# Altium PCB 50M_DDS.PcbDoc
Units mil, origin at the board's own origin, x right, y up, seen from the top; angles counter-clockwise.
Board outline 3260 x 1620 mil, 2 copper layers (Top Layer, Bottom Layer); 21 components, 21 nets, 79 pads, 5 vias.
Unrouted connection lines stored in the file: 2.
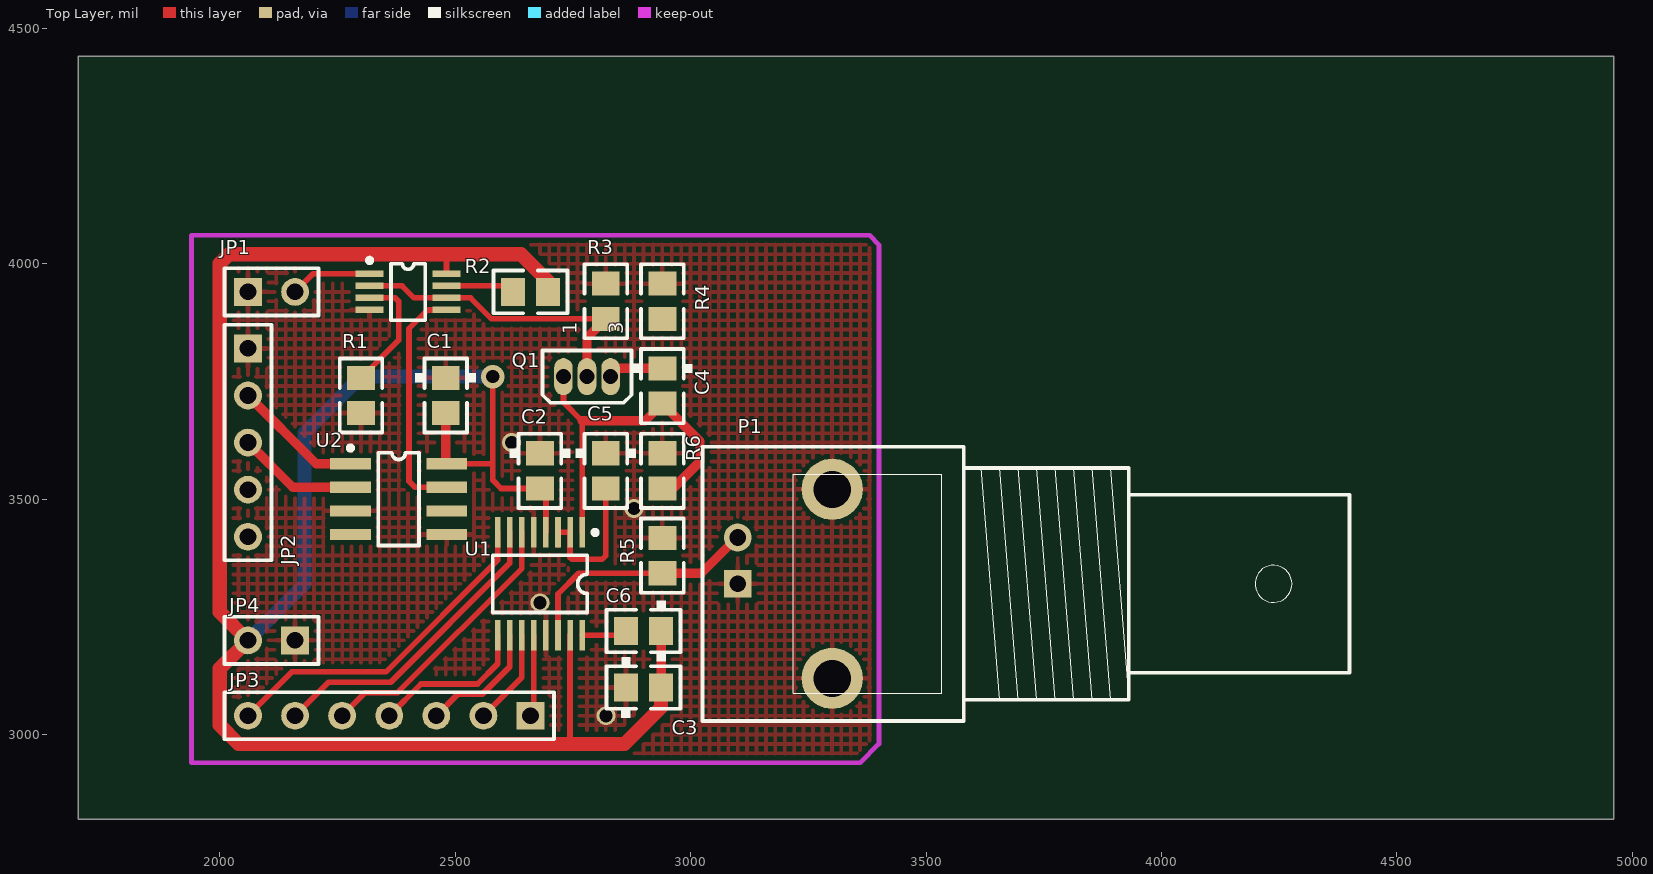
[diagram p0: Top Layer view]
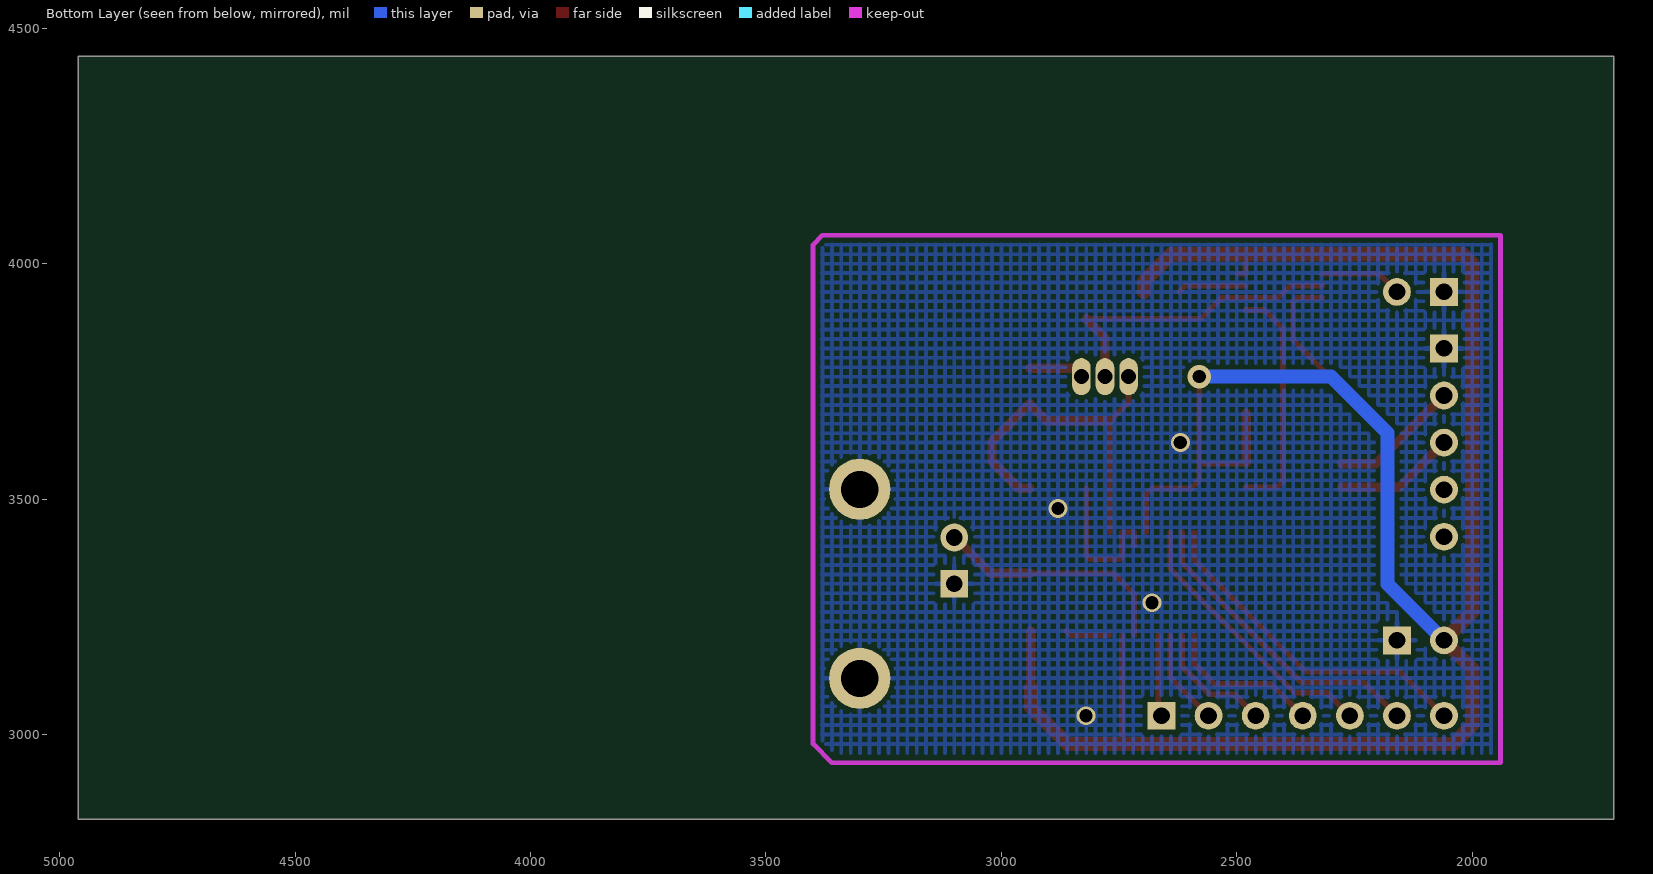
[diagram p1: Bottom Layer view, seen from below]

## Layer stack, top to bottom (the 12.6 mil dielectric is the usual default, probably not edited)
Top Layer: signal copper 1.4
Dielectric: dielectric 12.6, FR-4, Dk 4.8
Bottom Layer: signal copper 1.4

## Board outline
1700,4380 1700,2820 4960,2820 4960,4440 1700,4440

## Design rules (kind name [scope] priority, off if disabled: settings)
Clearance [All] p1: gap=10
ComponentClearance [All] p1: gap=10 collisioncheckmode=0
PolygonConnect [All] p1: connectstyle=Relief reliefconductorwidth=10 reliefentries=4 polygonreliefangle="90 Angle"
RoutingLayers [All] p1: top layer=Horizontal bottom layer=Vertical
RoutingVias [All] p1: holewidth=28 width=50 viastyle="Through Hole" minholewidth=28 minwidth=50 maxholewidth=28 maxwidth=50
SolderMaskExpansion [All] p1: expansion=4
TestPointUsage [All] p1: valid=0 allowmultiple=FALSE
Testpoint [All] p1: side=15 testpointundercomponent=TRUE minsize=40 maxsize=100 preferedsize=60 minholesize=0 maxholesize=40 preferedholesize=32 testpointgrid=1 style=1023 order=1234567890
Width [All] p1: maxlimit=50 minlimit=10 preferedwidth=10 toplayer_prefwidth=12 bottomlayer_prefwidth=30 minimp=50.000000 maximp=50.000000 favimp=50.000000
16 further rules are at their usual default settings.

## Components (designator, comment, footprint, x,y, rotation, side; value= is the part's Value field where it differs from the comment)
C1 "100pF" CC2012-0805 2480,3720 r270 top
C2 "100pF" CC2012-0805 2680,3560 r270 top
C3 "100pF" CC2012-0805 2900,3100 r0 top
C4 "510pF" CC2012-0805 2940,3740 r270 top
C5 "100pF" CC2012-0805 2820,3560 r270 top
C6 "100pF" CC2012-0805 2900,3220 r180 top
JP1 "Header 2" HDR1X2 2060,3940 r0 top locked
JP2 "Header 5" HDR1X5 2060,3820 r270 top locked
JP3 "Header 7" HDR1X7 2660,3040 r180 top locked
JP4 "Header 2" HDR1X2 2160,3200 r180 top locked
P1 "BNC" "BNC_RA CON" 3100,3320 r180 top
Q1 "MOSFET-N" BCY-W3/H.8 2780,3760 r90 top
R1 "4.7K" R2012-0805 2300,3720 r270 top
R2 "4.7K" R2012-0805 2660,3940 r0 top
R3 "50" R2012-0805 2820,3920 r270 top
R4 "1.5K" R2012-0805 2940,3920 r270 top
R5 "300" R2012-0805 2940,3380 r270 top
R6 "4.7K" R2012-0805 2940,3560 r270 top
U1 "AD9835" TSSO5X6-G16 2680,3320 r180 top
U2 "TLC5615" SO-G8 2380,3500 r270 top
? "ADG821" TSSO3X5-G8/X.35 2400,3940 r270 top

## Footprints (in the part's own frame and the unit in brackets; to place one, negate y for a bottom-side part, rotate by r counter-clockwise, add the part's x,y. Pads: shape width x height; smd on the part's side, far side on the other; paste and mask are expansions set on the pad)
BCY-W3/H.8 [mm]
  oval 2x1 hole 0.8: 1(0,1.27) 2(0,0) 3(0,-1.27)
  silkscreen extent -1.41,-2.41 1.41,2.41
"BNC_RA CON" [mm]
  rect 1.5x1.5 hole 0.9: 1(0,0)
  round 3.3 hole 2: 2(-5.1,5.1) 2(-5.1,-5.1)
  round 1.5 hole 0.9: 2(0,-2.5)
  silkscreen extent -33,-7.4 1.9,7.4
CC2012-0805 [mm]
  rect 1.3x1.5 smd: 1(-0.95,0) 2(0.95,0)
  silkscreen extent -2,-1.65 2,1.64
HDR1X2 [mm]
  rect 1.5x1.5 hole 0.9: 1(0,0)
  round 1.5 hole 0.9: 2(2.54,0)
  silkscreen extent -1.27,-1.27 3.81,1.27
HDR1X5 [mm]
  rect 1.5x1.5 hole 0.9: 1(0,0)
  round 1.5 hole 0.9: 2(2.54,0) 3(5.08,0) 4(7.62,0) 5(10.16,0)
  silkscreen extent -1.27,-1.27 11.43,1.27
HDR1X7 [mm]
  rect 1.5x1.5 hole 0.9: 1(0,0)
  round 1.5 hole 0.9: 2(2.54,0) 3(5.08,0) 4(7.62,0) 5(10.16,0) 6(12.7,0) 7(15.24,0)
  silkscreen extent -1.27,-1.27 16.51,1.27
R2012-0805 [mm]
  rect 1.3x1.5 smd: 1(-0.95,0) 2(0.95,0)
  silkscreen extent -2,-1.15 2,1.15
SO-G8 [mm]
  rect 0.6x2.2 smd: 1(-1.905,-2.6) 2(-0.635,-2.6) 3(0.635,-2.6) 4(1.905,-2.6) 5(1.905,2.6) 6(0.635,2.6) 7(-0.635,2.6) 8(-1.905,2.6)
  silkscreen extent -2.88,-2.72 2.5,1.1
TSSO3X5-G8/X.35 [mm]
  rect 0.35x1.5 smd: 1(-0.975,-2.075) 2(-0.325,-2.075) 3(0.325,-2.075) 4(0.975,-2.075) 5(0.975,2.075) 6(0.325,2.075) 7(-0.325,2.075) 8(-0.975,2.075)
  silkscreen extent -1.82,-2.2 1.52,0.92
TSSO5X6-G16 [mm]
  rect 0.3x1.65 smd: 1(-2.275,-2.775) 2(-1.625,-2.775) 3(-0.975,-2.775) 4(-0.325,-2.775) 5(0.325,-2.775) 6(0.975,-2.775) 7(1.625,-2.775) 8(2.275,-2.775) 9(2.275,2.775) 10(1.625,2.775) 11(0.975,2.775) 12(0.325,2.775) 13(-0.325,2.775) 14(-0.975,2.775) 15(-1.625,2.775) 16(-2.275,2.775)
  silkscreen extent -3.1,-2.9 2.55,1.55

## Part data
C1 C2 C3 C4 C5 C6: library part Cap, "Capacitor"
JP1 JP4: "Header, 2-Pin"
JP2: "Header, 5-Pin"
JP3: "Header, 7-Pin"
P1: "BNC Elbow Connector"
Q1: "N-Channel MOSFET"
R1 R2 R3 R4 R5 R6: library part Res1, "Resistor"
U1: "50 MHz CMOS / Complete DDS"
U2: "10bit DA Convertor"

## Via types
v1: diameter 40, hole 28, Top Layer to Bottom Layer, 4 vias
v2: diameter 50, hole 28, Top Layer to Bottom Layer, 1 vias

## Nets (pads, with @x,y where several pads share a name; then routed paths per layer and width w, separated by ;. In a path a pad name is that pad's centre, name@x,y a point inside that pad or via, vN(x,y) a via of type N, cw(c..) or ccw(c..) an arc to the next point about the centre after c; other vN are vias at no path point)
CLK: JP2.3 U2.2 | length 257
  Top Layer w20: JP2.3 2155,3525 U2.2
D: ?.2 ?.6 Q1.2 R3.2 | length 669.9
  Top Layer w12: ?.2 2387.2,3952.8 2412.8,3927.2 2532.8,3927.2 2577.4,3882.6 R3.2
  Top Layer w20: Q1.2 2780,3842.6 R3.2
DIN: JP2.2 U2.1 | length 277.7
  Top Layer w20: JP2.2 2205,3575 U2.1
FSEL: JP3.3 U1.10 | length 265.9
  Top Layer w12: JP3.3 2505.46,3085.46 2557.51,3085.46 2616.02,3143.98 U1.10
FSYNC: JP3.4 U1.9 | length 336.5
  Top Layer w12: JP3.4 2427.46,3107.46 2547.46,3107.46 2590.43,3150.43 U1.9
GND: ?.4 C1.1 C2.1 C3.1 C5.1 JP1.1 JP2.1 JP4.1 P1.1 P1.2@3300.79,3119.21 P1.2@3300.79,3520.79 R1.2 R3.1 R4.1 R5.1 R6.1 U1.5 U1.13 U2.3 U2.5
  other v1: 2820,3040 2680,3280 2880,3480 2620,3620
IN1: ?.7 JP2.5 R2.1 | length 146.2
  Top Layer w12: ?.7 2609.8,3952.8 R2.1
MCLK: JP3.5 U1.6 | length 607.7
  Top Layer w12: JP3.5@2280,3040 JP3.5 2309.03,3089.03 2377.91,3089.03 2641.61,3352.73 U1.6
Net_3: ?.3 R1.1 | length 260.4
  Top Layer w12: R1.1 2380,3837.4 2380,3920 2372.8,3927.2 ?.3
NetC4_1: C4.1 Q1.3 R4.2 | length 117.2
  Top Layer w20: Q1.3 2847.4,3777.4 C4.1
NetC5_2: C5.2 U1.2 U1.3 | length 330.1
  Top Layer w12: U1.3@2718.39,3401.61 U1.3 U1.2 2743.98,3376.02 2748.1,3371.9 2811.9,3371.9 2820,3380 C5.2
NetC6_2: C6.2 U1.16 | length 96.9
  Top Layer w12: U1.16 2853.35,3210.75 C6.2
NetP1_2: P1.2@3100,3418.43 R5.2 U1.14 | length 519.6
  Top Layer w12: U1.14 2718.39,3298.39 2762.6,3342.6 R5.2
  Top Layer w20: R5.2 3022.6,3342.6 P1.2@3100,3420
PSEL0: JP3.1 U1.12 | length 173.7
  Top Layer w12: JP3.1 2667.2,3047.2 U1.12
PSEL1: JP3.2 U1.11 | length 204.6
  Top Layer w12: JP3.2 2641.61,3121.61 U1.11
RSET: C4.2 Q1.1 R6.2 U1.1 | length 792.2
  Top Layer w12: Q1.1 2730,3705.76 2769.57,3666.19 U1.1
  Top Layer w20: 2769.57,3666.19 2903.59,3666.19 C4.2 3020,3622.6 3020,3580 2962.6,3522.6 R6.2
S1: ?.1 JP1.2 | length 174.2
  Top Layer w12: JP1.2 2198.39,3978.39 ?.1
S2: ?.5 U2.7 | length 505.8
  Top Layer w12: ?.5 2441.61,3901.61 2402,3862 2402,3538 2415,3525 U2.7
SCLK: JP3.6 U1.7 | length 655.5
  Top Layer w12: JP3.6 2231.03,3111.03 2363.07,3111.03 2616.02,3363.98 U1.7
SDATA: JP3.7 U1.8 | length 726.1
  Top Layer w12: JP3.7 2153.03,3133.03 2353.03,3133.03 2590.43,3370.43 U1.8
VCC: ?.8 C1.2 C2.2 C3.2 C6.1 JP4.2 R2.2 U1.4 U1.15 U2.8 | length 4793
  Top Layer w12: U2.8@2480,3577.36 U2.8 2575,3575 2580,3580 ; 2481.69,4018.31 ?.8 ?.8@2498.39,3978.39 ; v2(2580,3760) 2580,3540 2597.4,3522.6 C2.2 2692.8,3509.8 U1.4 ; 2740,2980 2743.98,2983.98 U1.15
  Top Layer w20: U2.8@2480,3577.36 C1.2 ; C3.2 C6.1
  Top Layer w30: R2.2 2697.4,3962.6 2640,4020 2020,4020 2000,4000 2000,3260 JP4.2 2000,3140 2000,3020 2040,2980 2860,2980 2937.4,3057.4 C3.2
  Bottom Layer w30: JP4.2 2180,3320 2180,3640 2300,3760 v2(2580,3760)
pads on no net: JP2.4 U2.4 U2.6

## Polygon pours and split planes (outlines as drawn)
GND on Top Layer (hatched 90Degree grid 20 track 8, remove dead copper): 1960,4040 1960,2940 3400,2940 3400,4060 1960,4060
GND on Bottom Layer (hatched 90Degree grid 20 track 8, remove dead copper): 1960,4040 1960,2960 3400,2960 3400,4060 1960,4060

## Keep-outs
Keep-Out Layer:
  lines w10: 1940,2940 3360,2940 3400,2980 3400,4040 3380,4060 1940,4060 1940,4040 1940,2940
